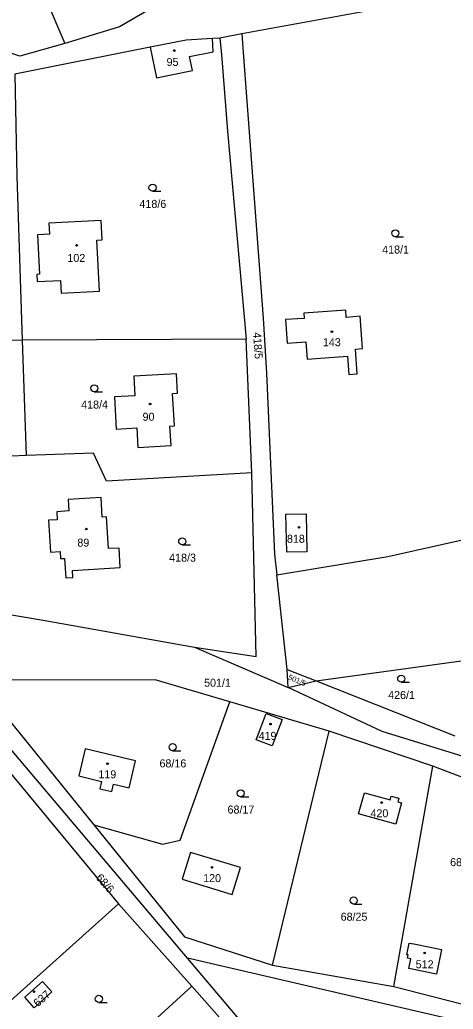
# Model space of a CAD drawing. Extents: x -725728 to -720881, y -1068679 to -1063504.
# Drawn here: x -724248.4 to -724156.4, y -1067398.3 to -1067188.2 of the extents above; entities that cross this region are included whole.
import ezdxf

# ---------------------------------------------------------------- set-up
doc = ezdxf.new("R2010")
doc.units = 0
for name, color, linetype in [('Hranice parcel', 7, 'Continuous'), ('Parcelní čísla', 7, 'Continuous'), ('Značky budov', 7, 'Continuous'), ('Značky kultur', 7, 'Continuous')]:
    doc.layers.add(name, color=color, linetype=linetype)

# ---------------------------------------------------------------- blocks, each defined once
blk = doc.blocks.new('4.02_3')
at = {"layer": 'Značky budov'}
blk.add_circle((-0.001, 0), 0.0175, dxfattribs=at)
blk = doc.blocks.new('4.02_4')
at = {"layer": 'Značky budov'}
blk.add_circle((-0.001, 0), 0.0175, dxfattribs=at)
blk = doc.blocks.new('3.04_2')
at = {"layer": 'Značky kultur'}
blk.add_line((0.001, 0), (0.176, 0), dxfattribs=at)
blk.add_circle((0.001, 0.075), 0.075, dxfattribs=at)
blk = doc.blocks.new('3.04_3')
at = {"layer": 'Značky kultur'}
blk.add_line((0.001, 0), (0.176, 0), dxfattribs=at)
blk.add_circle((0.001, 0.075), 0.075, dxfattribs=at)

msp = doc.modelspace()

# ---------------------------------------------------------------- linework, layer by layer
at = {"layer": 'Hranice parcel'}
for p, q in [((-724248.33, -1067171.1), (-724238.81, -1067193.3)), ((-724173.25, -1067186.11), (-724201.25, -1067191.18)), ((-724201.25, -1067191.18), (-724205.91, -1067192.17)), ((-724205.91, -1067192.17), (-724207.48, -1067192.24)), ((-724205.91, -1067192.17), (-724205.56, -1067195.59)), ((-724220.69, -1067194.05), (-724249.46, -1067199.78)), ((-724191.98, -1067251.9), (-724191.63, -1067256.89)), ((-724247.88, -1067256.27), (-724270.88, -1067256.63)), ((-724200.35, -1067256.03), (-724247.88, -1067256.27)), ((-724247.88, -1067256.27), (-724247.06, -1067280.77)), ((-724199.14, -1067284.42), (-724200.35, -1067256.03)), ((-724247.06, -1067280.77), (-724250.06, -1067280.93)), ((-724194.28, -1067301.68), (-724193.8, -1067306.12)), ((-724191.65, -1067326.21), (-724193.8, -1067306.12)), ((-724211.28, -1067321.48), (-724191.42, -1067330.05)), ((-724185.48, -1067328.64), (-724146.86, -1067323.24)), ((-724191.65, -1067326.21), (-724185.48, -1067328.64)), ((-724191.42, -1067330.05), (-724191.65, -1067326.21)), ((-724191.42, -1067330.05), (-724185.48, -1067328.64)), ((-724185.48, -1067328.64), (-724155.99, -1067340.27)), ((-724212.77, -1067387.5), (-724259.04, -1067332.89)), ((-724253.89, -1067333.02), (-724232.66, -1067359.21)), ((-724182.7, -1067339.32), (-724203.77, -1067333.07)), ((-724194.76, -1067388.98), (-724182.7, -1067339.32)), ((-724160.72, -1067346.75), (-724182.7, -1067339.32)), ((-724168.96, -1067393.53), (-724160.72, -1067346.75)), ((-724144.82, -1067352.77), (-724160.72, -1067346.75)), ((-724251.09, -1067347.37), (-724227.45, -1067375.94)), ((-724271.37, -1067415.38), (-724227.45, -1067375.94)), ((-724227.45, -1067375.94), (-724211.88, -1067393.47)), ((-724193.46, -1067410.3), (-724212.77, -1067387.5)), ((-724194.76, -1067388.98), (-724168.96, -1067393.53)), ((-724254.08, -1067431.8), (-724211.88, -1067393.47)), ((-724211.88, -1067393.47), (-724195.39, -1067412.03)), ((-724168.96, -1067393.53), (-724154.63, -1067397.2))]:
    msp.add_line(p, q, dxfattribs=at)
for points in [[(-724205.22, -1067159.99), (-724203.14, -1067167.35), (-724213.41, -1067181.65), (-724227.23, -1067189.7), (-724238.81, -1067193.3)], [(-724238.81, -1067193.3), (-724248.42, -1067195.98), (-724282.2, -1067184.67)], [(-724201.25, -1067191.18), (-724200.95, -1067195.18), (-724196.72, -1067251.58), (-724196.04, -1067263.27), (-724194.28, -1067301.68)], [(-724207.48, -1067192.24), (-724213.04, -1067192.53), (-724220.69, -1067194.05)], [(-724220.69, -1067194.05), (-724219.4, -1067200.53), (-724211.75, -1067199), (-724212.34, -1067196.06), (-724207.33, -1067195.06), (-724207.48, -1067192.24)], [(-724205.56, -1067195.59), (-724204.27, -1067211.89), (-724200.35, -1067256.03)], [(-724249.46, -1067199.78), (-724249.04, -1067221.44), (-724247.88, -1067256.27)], [(-724231.49, -1067245.84), (-724232.02, -1067235), (-724230.92, -1067234.94), (-724231.14, -1067230.85), (-724242.22, -1067231.44), (-724242.1, -1067233.78), (-724244.64, -1067233.92), (-724244.2, -1067242.26), (-724244.8, -1067242.29), (-724244.72, -1067243.84), (-724239.72, -1067243.57), (-724239.58, -1067246.27), (-724231.49, -1067245.84)], [(-724191.63, -1067256.89), (-724187.66, -1067256.63), (-724187.4, -1067260.3), (-724178.8, -1067259.66), (-724178.51, -1067263.57), (-724176.75, -1067263.44), (-724177.14, -1067258.16), (-724175.62, -1067258.05), (-724176.1, -1067251.18), (-724179.07, -1067251.43), (-724179.2, -1067249.92), (-724188.09, -1067250.51), (-724188.01, -1067251.63), (-724191.98, -1067251.9)], [(-724223.31, -1067279.06), (-724216.27, -1067278.66), (-724216.51, -1067274.51), (-724215.57, -1067274.46), (-724215.96, -1067267.62), (-724214.91, -1067267.55), (-724215.15, -1067263.4), (-724224.19, -1067263.93), (-724223.95, -1067268.08), (-724228.29, -1067268.33), (-724227.9, -1067275.15), (-724223.55, -1067274.9), (-724223.31, -1067279.06)], [(-724199.14, -1067284.42), (-724230, -1067286.22), (-724232.77, -1067280.29), (-724247.06, -1067280.77)], [(-724211.28, -1067321.48), (-724198.19, -1067323.44), (-724199.14, -1067284.42)], [(-724240.45, -1067294.39), (-724242.3, -1067294.49), (-724241.9, -1067301.28), (-724239.81, -1067301.16), (-724239.72, -1067302.66), (-724238.87, -1067302.61), (-724238.62, -1067306.73), (-724237.13, -1067306.64), (-724237.22, -1067305.15), (-724227.08, -1067304.55), (-724227.32, -1067300.43), (-724229.58, -1067300.51), (-724229.97, -1067293.77), (-724230.87, -1067293.82), (-724231.11, -1067289.67), (-724238.1, -1067290.07), (-724237.95, -1067292.54), (-724240.55, -1067292.69), (-724240.45, -1067294.39)], [(-724191.87, -1067293.25), (-724187.6, -1067293.17), (-724187.43, -1067301.21), (-724191.72, -1067301.29), (-724191.87, -1067293.25)], [(-724193.8, -1067306.12), (-724170.26, -1067302.2), (-724147.44, -1067297.08)], [(-724252.23, -1067314.24), (-724243.41, -1067315.74), (-724211.28, -1067321.48)], [(-724203.77, -1067333.07), (-724219.65, -1067328.37), (-724257.56, -1067328.49)], [(-724018.75, -1067367.26), (-724044.28, -1067367.29), (-724124.91, -1067354.08), (-724142.81, -1067348.22), (-724171.47, -1067339.34), (-724191.42, -1067330.05)], [(-724232.66, -1067359.21), (-724218.07, -1067363.28), (-724214.37, -1067362.44), (-724203.77, -1067333.07)], [(-724196.08, -1067335.54), (-724192.71, -1067336.82), (-724194.84, -1067342.43), (-724198.21, -1067341.15), (-724196.08, -1067335.54)], [(-724234.5, -1067343.04), (-724235.88, -1067348.77), (-724231.03, -1067349.95), (-724231.4, -1067351.51), (-724228.87, -1067352.12), (-724228.5, -1067350.56), (-724225.19, -1067351.36), (-724223.81, -1067345.62), (-724234.5, -1067343.04)], [(-724176.48, -1067356.84), (-724175.23, -1067352.37), (-724169.73, -1067353.87), (-724169.52, -1067353.11), (-724167.91, -1067353.55), (-724168.12, -1067354.31), (-724167.31, -1067354.53), (-724168.57, -1067359.05), (-724176.48, -1067356.84)], [(-724232.66, -1067359.21), (-724213.39, -1067382.98), (-724194.76, -1067388.98)], [(-724212.16, -1067365.04), (-724213.89, -1067370.73), (-724203.27, -1067373.96), (-724201.54, -1067368.27), (-724212.16, -1067365.04)], [(-724165.96, -1067386.81), (-724166.2, -1067386.76), (-724165.7, -1067384.28), (-724164.7, -1067384.48), (-724158.85, -1067385.66), (-724159.91, -1067390.91), (-724165.79, -1067389.72), (-724165.37, -1067387.64), (-724166.09, -1067387.49), (-724165.96, -1067386.81)], [(-724041.46, -1067435.09), (-724154.53, -1067401.02), (-724212.77, -1067387.5)], [(-724243.58, -1067392.42), (-724241.59, -1067394.64), (-724245.32, -1067398.03), (-724247.33, -1067395.8), (-724243.58, -1067392.42)]]:
    msp.add_lwpolyline(points, dxfattribs=at)

# ---------------------------------------------------------------- block references
at = {"layer": 'Značky budov', "xscale": 10, "yscale": 10}
for name, p in [('4.02_3', (-724215.57, -1067194.76)), ('4.02_4', (-724236.32, -1067236.14)), ('4.02_3', (-724182.11, -1067254.46)), ('4.02_3', (-724220.71, -1067269.82)), ('4.02_3', (-724234.26, -1067296.37)), ('4.02_3', (-724189.1, -1067296.01)), ('4.02_3', (-724195.16, -1067337.8)), ('4.02_4', (-724229.76, -1067346.18)), ('4.02_3', (-724171.53, -1067354.46)), ('4.02_3', (-724207.58, -1067368.22)), ('4.02_4', (-724162.41, -1067386.4)), ('4.02_3', (-724245.38, -1067394.62))]:
    msp.add_blockref(name, p, dxfattribs=at)
at = {"layer": 'Značky kultur', "xscale": 10, "yscale": 10}
for name, p in [('3.04_3', (-724220.22, -1067224.63)), ('3.04_2', (-724168.66, -1067234.32)), ('3.04_2', (-724232.59, -1067267.24)), ('3.04_2', (-724213.91, -1067299.75)), ('3.04_3', (-724167.41, -1067328.91)), ('3.04_2', (-724215.96, -1067343.44)), ('3.04_2', (-724201.51, -1067353.24)), ('3.04_2', (-724177.5, -1067376)), ('3.04_3', (-724231.62, -1067396.89))]:
    msp.add_blockref(name, p, dxfattribs=at)

# ---------------------------------------------------------------- texts
at = {"layer": 'Parcelní čísla'}
for s, p in [('95', (-724217.22, -1067198.03)), ('418/6', (-724222.99, -1067228.18)), ('418/1', (-724171.44, -1067237.87)), ('102', (-724238.29, -1067239.66)), ('143', (-724184.04, -1067257.55)), ('418/4', (-724235.36, -1067270.79)), ('90', (-724222.32, -1067273.38)), ('89', (-724236.17, -1067300.11)), ('818', (-724191.67, -1067299.29)), ('418/3', (-724216.68, -1067303.3)), ('501/1', (-724209.26, -1067329.86)), ('426/1', (-724170.18, -1067332.46)), ('419', (-724197.69, -1067341.14)), ('68/16', (-724218.73, -1067346.99)), ('119', (-724231.7, -1067349.3)), ('68/17', (-724204.28, -1067356.79)), ('420', (-724173.93, -1067357.58)), ('68/26', (-724157.02, -1067367.96)), ('120', (-724209.46, -1067371.35)), ('68/25', (-724180.27, -1067379.55)), ('512', (-724164.33, -1067389.65))]:
    msp.add_text(s, height=1.7, dxfattribs=at).set_placement(p)
for s, height, rotation, p in [('418/5', 1.7, 274, (-724198.88, -1067254.63)), ('501/5', 1.14, 337, (-724191.55, -1067328.26)), ('68/6', 1.7, 311, (-724232.38, -1067370.48)), ('637', 1.7, 41, (-724244.59, -1067397.94))]:
    msp.add_text(s, height=height, rotation=rotation, dxfattribs=at).set_placement(p)

doc.saveas('drawing.dxf')
